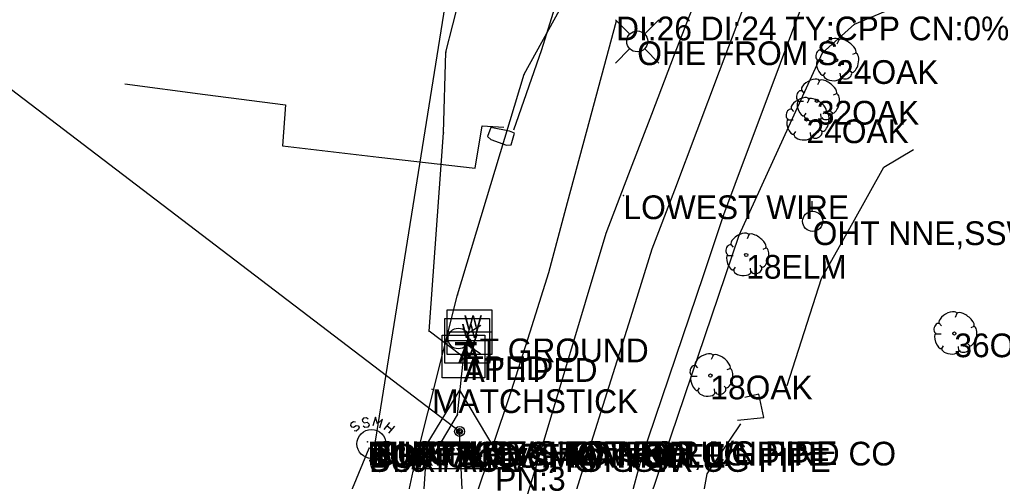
# Model space of a CAD drawing. Extents: x 997398 to 1003416, y 334596 to 337085.
# Drawn here: x 999162 to 999369.2, y 335640.6 to 335737.9 of the extents above; entities that cross this region are included whole.
import ezdxf

# ---------------------------------------------------------------- set-up
doc = ezdxf.new("R2010")
doc.units = 0
for name, color, linetype in [('Default', 7, 'Continuous'), ('S_CURB', 7, 'Continuous'), ('S_DITCHLINE', 7, 'Continuous'), ('S_EDGE_CONCRETE', 7, 'Continuous'), ('S_EDGE_PAVEMENT', 7, 'Continuous'), ('S_ELECTRIC_UTILITIES_ANNOT', 7, 'Continuous'), ('S_FIBER_OPTIC_CABLE', 7, 'Continuous'), ('S_FIBER_OPTIC_CABLE_ANNOT', 7, 'Continuous'), ('S_GRD_PT_SYM', 7, 'Continuous'), ('S_MANHOLE_ANNOT', 7, 'Continuous'), ('S_MISC_TOPO_POINT', 7, 'Continuous'), ('S_PAVEMENT_CROWN', 7, 'Continuous'), ('S_PRIMARY_CTL', 7, 'Continuous'), ('S_PRIMARY_CTL_ANNOT', 7, 'Continuous'), ('S_SANITARY_SEWER', 7, 'Continuous'), ('S_SANITARY_SEWER_ANNOT', 7, 'Continuous'), ('S_SIDE_DRAIN_ANNOT', 7, 'Continuous'), ('S_TELEPHONE_UTILITIES', 7, 'Continuous'), ('S_TELEPHONE_UTILITIES_ANNOT', 7, 'Continuous'), ('S_TREE', 7, 'Continuous'), ('S_TREE_ANNOT', 7, 'Continuous'), ('S_UTILITY_POLE', 7, 'Continuous'), ('S_UTILITY_POLE_ANNOT', 7, 'Continuous'), ('S_UTL_PT_SYM', 7, 'Continuous'), ('S_WATER_UTILITIES', 7, 'Continuous'), ('S_WATER_UTILITIES_ANNOT', 7, 'Continuous')]:
    doc.layers.add(name, color=color, linetype=linetype)

msp = doc.modelspace()

# ---------------------------------------------------------------- linework, layer by layer
at = {"layer": 'Default'}
for p, q in [((999254.77, 335651.12), (998964.3, 335872.43)), ((999272.07, 335256.17), (999254.77, 335651.12))]:
    msp.add_line(p, q, dxfattribs=at)
at = {"layer": 'S_CURB'}
msp.add_lwpolyline([(999266.19, 335714.69), (999272.09, 335731.57), (999275.58, 335742.68), (999279.48, 335749.62), (999286.56, 335754.18), (999294.45, 335756.63), (999296.19, 335756.83)], dxfattribs=at)
at = {"layer": 'S_DITCHLINE'}
for points in [[(999287.81, 335737.53), (999281.43, 335714.1), (999277.48, 335699.31), (999273.53, 335684.53), (999269.56, 335672.01), (999265.58, 335659.49), (999257.69, 335636), (999252.77, 335619.88)], [(999323.8, 335660.76), (999331.07, 335683.36), (999337.63, 335695.08), (999344.19, 335706.81), (999350.44, 335710.54)], [(999279.93, 335526.04), (999283.42, 335541.33), (999286.91, 335556.62), (999292.97, 335577.81), (999299.03, 335599), (999303, 335620.58), (999306.97, 335642.16), (999314.07, 335652.72)]]:
    msp.add_lwpolyline(points, dxfattribs=at)
at = {"layer": 'S_EDGE_CONCRETE'}
for points in [[(999266.37, 335713.96), (999265.31, 335714.36), (999261.35, 335715.12), (999260.65, 335713.27), (999261.34, 335712.62), (999264.66, 335711.39), (999265.63, 335711.53)], [(999265.63, 335711.53), (999266.37, 335713.96)], [(999313.33, 335653.52), (999318.9, 335654.07), (999317.87, 335658.97), (999314.93, 335658.3)]]:
    msp.add_lwpolyline(points, dxfattribs=at)
at = {"layer": 'S_EDGE_PAVEMENT'}
for points in [[(999259.87, 335596.96), (999264.04, 335615.85), (999268.21, 335634.73), (999272.57, 335649.27), (999276.93, 335663.8), (999281.3, 335678.34), (999285.66, 335692.87), (999290.47, 335705.41), (999295.28, 335717.95), (999300.08, 335730.5), (999304.89, 335743.04), (999311.07, 335757.48), (999317.24, 335771.92), (999323.96, 335787.59), (999330.67, 335803.27), (999334.33, 335812.1)], [(999352.59, 335804.28), (999348.8, 335795.55), (999343.98, 335783.6), (999339.17, 335771.64), (999334.35, 335759.69), (999329.54, 335747.73), (999324.76, 335734.99), (999319.98, 335722.25), (999315.21, 335709.51), (999310.43, 335696.77), (999306.09, 335683.91), (999301.75, 335671.05), (999297.41, 335658.19), (999293.07, 335645.33), (999289.63, 335632.59), (999286.2, 335619.85), (999282.76, 335607.12), (999279.33, 335594.38)], [(999184.24, 335724.34), (999201.16, 335722.13), (999218.08, 335719.91), (999217.45, 335711.3), (999237.76, 335708.93), (999258.08, 335706.56), (999259.56, 335715.48), (999264.13, 335715.19)]]:
    msp.add_lwpolyline(points, dxfattribs=at)
at = {"layer": 'S_FIBER_OPTIC_CABLE'}
for p, q in [((999268.37, 335726.35), (999282.47, 335752.03)), ((999251.87, 335731.03), (999255.29, 335744.38)), ((999338.02, 335736.93), (999346.74, 335740.59)), ((999331.26, 335730.91), (999338.02, 335736.93)), ((999251.36, 335714.01), (999251.87, 335731.03)), ((999313.68, 335692.48), (999331.26, 335730.91)), ((999254.36, 335679.9), (999268.37, 335726.35)), ((999248.33, 335672.22), (999251.36, 335714.01)), ((999295.04, 335637.34), (999313.68, 335692.48)), ((999245.02, 335642.72), (999254.36, 335679.9)), ((999255.06, 335667.18), (999248.33, 335672.22)), ((999254.35, 335654.64), (999255.61, 335666.56)), ((999255.61, 335666.56), (999255.06, 335667.18)), ((999247.58, 335643.26), (999254.35, 335654.64)), ((999239.4, 335617.34), (999245.02, 335642.72)), ((999246.94, 335633.43), (999247.58, 335643.26))]:
    msp.add_line(p, q, dxfattribs=at)
at = {"layer": 'S_GRD_PT_SYM'}
for points in [[(999289.32, 335700.84), (999289.32, 335700.89), (999289.32, 335700.84), (999289.27, 335700.84), (999289.32, 335700.84), (999289.32, 335700.79), (999289.32, 335700.84), (999289.37, 335700.84)], [(999235.34, 335648.94), (999235.34, 335648.99), (999235.34, 335648.94), (999235.29, 335648.94), (999235.34, 335648.94), (999235.34, 335648.89), (999235.34, 335648.94), (999235.39, 335648.94)], [(999237.04, 335649.04), (999237.04, 335649.09), (999237.04, 335649.04), (999236.99, 335649.04), (999237.04, 335649.04), (999237.04, 335648.99), (999237.04, 335649.04), (999237.09, 335649.04)], [(999235.68, 335647.6), (999235.68, 335647.65), (999235.68, 335647.6), (999235.63, 335647.6), (999235.68, 335647.6), (999235.68, 335647.55), (999235.68, 335647.6), (999235.73, 335647.6)]]:
    msp.add_lwpolyline(points, dxfattribs=at)
at = {"layer": 'S_PAVEMENT_CROWN'}
msp.add_lwpolyline([(999277.22, 335631.74), (999281.77, 335646.2), (999286.31, 335660.66), (999290.86, 335675.12), (999295.4, 335689.58), (999300.12, 335702.05), (999304.83, 335714.52), (999309.55, 335726.99), (999314.27, 335739.46), (999320.77, 335755.48), (999327.27, 335771.5), (999333.35, 335785.79), (999339.42, 335800.08), (999343.03, 335808.38)], dxfattribs=at)
at = {"layer": 'S_PRIMARY_CTL'}
for p, q in [((999254.77, 335659.82), (999244.74, 335643.31)), ((999254.77, 335659.82), (999264.59, 335643.31)), ((999244.74, 335643.31), (999264.59, 335643.31))]:
    msp.add_line(p, q, dxfattribs=at)
for radius in [1.04, 0.609, 0.344]:
    msp.add_circle((999254.77, 335651.12), radius, dxfattribs=at)
at = {"layer": 'S_SANITARY_SEWER'}
for p, q in [((999237.04, 335649.04), (999255.03, 335761.15)), ((999231.87, 335652.78), (999231.79, 335652.39)), ((999231.79, 335652.39), (999231.99, 335652.12)), ((999232.41, 335653.17), (999231.87, 335652.78)), ((999231.99, 335652.12), (999232.41, 335652.01)), ((999232.84, 335653.09), (999232.41, 335653.17)), ((999232.41, 335652.01), (999232.96, 335652.35)), ((999232.96, 335652.35), (999233.42, 335652.28)), ((999233.42, 335652.28), (999233.58, 335652.01)), ((999233.58, 335652.01), (999233.5, 335651.58)), ((999238.85, 335651.54), (999240.09, 335653.01)), ((999239.5, 335652.32), (999240.47, 335651.5)), ((999241.05, 335652.2), (999239.81, 335650.73)), ((999232.96, 335651.19), (999232.57, 335651.27)), ((999233.5, 335651.58), (999232.96, 335651.19)), ((999196.73, 335553), (999235.68, 335647.6))]:
    msp.add_line(p, q, dxfattribs=at)
for points in [[(999237.95, 335651.85), (999238.5, 335653.71), (999237.45, 335652.7), (999237.06, 335654.14), (999236.52, 335652.28)], [(999235.51, 335653.71), (999235.16, 335653.98), (999234.51, 335653.9), (999234.27, 335653.56), (999234.31, 335653.25), (999234.66, 335652.94), (999235.28, 335653.05), (999235.67, 335652.74), (999235.71, 335652.43), (999235.44, 335652.04), (999234.82, 335651.97), (999234.47, 335652.24)]]:
    msp.add_lwpolyline(points, dxfattribs=at)
msp.add_circle((999236.2, 335648.48), 3.05, dxfattribs=at)
at = {"layer": 'S_TELEPHONE_UTILITIES'}
msp.add_lwpolyline([(999251.07, 335662.43), (999251.07, 335671.43), (999260.07, 335671.43), (999260.07, 335662.43)], close=True, dxfattribs=at)
at = {"layer": 'S_TREE'}
for p, q in [((999334.71, 335733.58), (999334.32, 335732.72)), ((999330.91, 335731.56), (999331.41, 335730.98)), ((999338.27, 335730.79), (999337.61, 335730.51)), ((999330.25, 335729.24), (999331.38, 335729.24)), ((999331.41, 335726.06), (999331.88, 335726.76)), ((999335.1, 335725.79), (999335.02, 335726.56)), ((999337.5, 335726.68), (999337.03, 335727.1)), ((999330.63, 335725.01), (999330.25, 335724.16)), ((999326.84, 335722.99), (999327.34, 335722.41)), ((999326.18, 335720.67), (999327.3, 335720.67)), ((999328.45, 335721.1), (999328.07, 335720.25)), ((999334.2, 335722.22), (999333.54, 335721.95)), ((999324.66, 335719.08), (999325.16, 335718.5)), ((999332.02, 335718.31), (999331.36, 335718.04)), ((999333.42, 335718.11), (999332.96, 335718.54)), ((999324, 335716.76), (999325.12, 335716.76)), ((999327.34, 335717.49), (999327.8, 335718.19)), ((999331.02, 335717.22), (999330.94, 335718)), ((999325.16, 335713.58), (999325.62, 335714.28)), ((999328.84, 335713.31), (999328.76, 335714.08)), ((999331.24, 335714.2), (999330.78, 335714.63)), ((999315.75, 335692.54), (999315.36, 335691.69)), ((999311.95, 335690.52), (999312.46, 335689.94)), ((999319.31, 335689.75), (999318.66, 335689.48)), ((999311.29, 335688.2), (999312.42, 335688.2)), ((999312.46, 335685.02), (999312.92, 335685.72)), ((999316.14, 335684.75), (999316.06, 335685.52)), ((999318.54, 335685.64), (999318.07, 335686.07)), ((999359.62, 335675.99), (999359.23, 335675.14)), ((999355.82, 335673.98), (999356.32, 335673.39)), ((999363.18, 335673.2), (999362.52, 335672.93)), ((999355.16, 335671.65), (999356.28, 335671.65)), ((999356.32, 335668.47), (999356.79, 335669.17)), ((999360, 335668.2), (999359.93, 335668.98)), ((999362.41, 335669.09), (999361.94, 335669.52)), ((999308.2, 335667.13), (999307.81, 335666.28)), ((999304.4, 335665.11), (999304.9, 335664.53)), ((999303.74, 335662.79), (999304.86, 335662.79)), ((999311.76, 335664.34), (999311.1, 335664.07)), ((999304.9, 335659.61), (999305.37, 335660.31)), ((999310.99, 335660.23), (999310.52, 335660.66)), ((999308.58, 335659.34), (999308.51, 335660.11))]:
    msp.add_line(p, q, dxfattribs=at)
for centre in [(999334.15, 335729.33), (999330.08, 335720.76), (999327.9, 335716.85), (999315.19, 335688.29), (999359.06, 335671.75), (999307.64, 335662.88)]:
    msp.add_circle(centre, 0.341, dxfattribs=at)
for centre, major_axis, ratio, start_param, end_param in [((999332.81, 335732.53), (1.86, 1.08), 0.471018, 0, 3.141593), ((999336.47, 335732.21), (-1.81, 1.36), 0.405113, 3.141593, 6.283186), ((999330.58, 335730.42), (0.31, 1.03), 0.646762, 0, 3.141593), ((999337.82, 335728.8), (0.46, 2.04), 0.482994, 3.141593, 6.283185), ((999330.88, 335727.77), (-0.61, 1.6), 0.420543, 6.283185, 9.424777), ((999336.3, 335726.28), (1.09, 0.46), 0.711534, 3.141592, 6.283185), ((999328.74, 335723.97), (1.86, 1.08), 0.471018, 0, 3.141593), ((999332.39, 335723.64), (-1.81, 1.36), 0.405113, 3.141593, 6.283186), ((999333.34, 335725.99), (-1.83, 0.19), 0.529943, 0, 3.141593), ((999326.5, 335721.85), (0.31, 1.03), 0.646762, 0, 3.141593), ((999326.56, 335720.06), (1.86, 1.08), 0.471018, 0, 3.141593), ((999326.81, 335719.2), (-0.61, 1.6), 0.420543, 6.283185, 9.424777), ((999330.21, 335719.73), (-1.81, 1.36), 0.405113, 3.141593, 6.283186), ((999333.75, 335720.23), (0.46, 2.04), 0.482994, 3.141593, 6.283185), ((999324.32, 335717.94), (0.31, 1.03), 0.646762, 0, 3.141593), ((999331.57, 335716.32), (0.46, 2.04), 0.482994, 3.141593, 6.283185), ((999324.63, 335715.29), (-0.61, 1.6), 0.420543, 6.283185, 9.424777), ((999329.27, 335717.42), (-1.83, 0.19), 0.529943, 0, 3.141593), ((999332.23, 335717.71), (1.09, 0.46), 0.711534, 3.141592, 6.283185), ((999330.05, 335713.8), (1.09, 0.46), 0.711534, 3.141592, 6.283185), ((999327.09, 335713.51), (-1.83, 0.19), 0.529943, 0, 3.141593), ((999313.86, 335691.49), (1.86, 1.08), 0.471018, 0, 3.141593), ((999317.51, 335691.17), (-1.81, 1.36), 0.405113, 3.141593, 6.283186), ((999311.62, 335689.38), (0.31, 1.03), 0.646762, 0, 3.141593), ((999318.87, 335687.76), (0.46, 2.04), 0.482994, 3.141593, 6.283185), ((999311.93, 335686.73), (-0.61, 1.6), 0.420543, 6.283185, 9.424777), ((999314.39, 335684.95), (-1.83, 0.19), 0.529943, 0, 3.141593), ((999317.34, 335685.24), (1.09, 0.46), 0.711534, 3.141592, 6.283185), ((999357.72, 335674.95), (1.86, 1.08), 0.471018, 0, 3.141593), ((999361.38, 335674.62), (-1.81, 1.36), 0.405113, 3.141593, 6.283186), ((999355.49, 335672.83), (0.31, 1.03), 0.646762, 0, 3.141593), ((999362.73, 335671.22), (0.46, 2.04), 0.482994, 3.141593, 6.283185), ((999355.79, 335670.18), (-0.61, 1.6), 0.420543, 6.283185, 9.424777), ((999358.25, 335668.4), (-1.83, 0.19), 0.529943, 0, 3.141593), ((999361.21, 335668.69), (1.09, 0.46), 0.711534, 3.141592, 6.283185), ((999306.3, 335666.09), (1.86, 1.08), 0.471018, 0, 3.141593), ((999309.96, 335665.76), (-1.81, 1.36), 0.405113, 3.141593, 6.283186), ((999304.07, 335663.97), (0.31, 1.03), 0.646762, 0, 3.141593), ((999311.31, 335662.35), (0.46, 2.04), 0.482994, 3.141593, 6.283185), ((999304.37, 335661.32), (-0.61, 1.6), 0.420543, 6.283185, 9.424777), ((999309.79, 335659.83), (1.09, 0.46), 0.711534, 3.141592, 6.283185), ((999306.83, 335659.54), (-1.83, 0.19), 0.529943, 0, 3.141593)]:
    msp.add_ellipse(centre, major_axis=major_axis, ratio=ratio, start_param=start_param, end_param=end_param, dxfattribs=at)
at = {"layer": 'S_UTILITY_POLE'}
for p, q in [((999290.62, 335734.87), (999287.64, 335737.86)), ((999293.8, 335734.87), (999296.78, 335737.86)), ((999290.62, 335731.69), (999287.64, 335728.71)), ((999293.8, 335731.69), (999296.78, 335728.71)), ((999329.07, 335697.52), (999329.07, 335699.63))]:
    msp.add_line(p, q, dxfattribs=at)
for centre, radius in [((999292.22, 335733.29), 2.21), ((999329.2, 335695.38), 2.13)]:
    msp.add_circle(centre, radius, dxfattribs=at)
at = {"layer": 'S_UTL_PT_SYM'}
for points in [[(999338.02, 335736.93), (999338.02, 335736.98), (999338.02, 335736.93), (999337.97, 335736.93), (999338.02, 335736.93), (999338.02, 335736.88), (999338.02, 335736.93), (999338.07, 335736.93)], [(999251.87, 335731.03), (999251.87, 335731.08), (999251.87, 335731.03), (999251.82, 335731.03), (999251.87, 335731.03), (999251.87, 335730.98), (999251.87, 335731.03), (999251.92, 335731.03)], [(999331.26, 335730.91), (999331.26, 335730.96), (999331.26, 335730.91), (999331.21, 335730.91), (999331.26, 335730.91), (999331.26, 335730.86), (999331.26, 335730.91), (999331.31, 335730.91)], [(999268.37, 335726.35), (999268.37, 335726.4), (999268.37, 335726.35), (999268.32, 335726.35), (999268.37, 335726.35), (999268.37, 335726.3), (999268.37, 335726.35), (999268.42, 335726.35)], [(999251.36, 335714.01), (999251.36, 335714.06), (999251.36, 335714.01), (999251.31, 335714.01), (999251.36, 335714.01), (999251.36, 335713.96), (999251.36, 335714.01), (999251.41, 335714.01)], [(999289.32, 335700.84), (999289.32, 335700.89), (999289.32, 335700.84), (999289.27, 335700.84), (999289.32, 335700.84), (999289.32, 335700.79), (999289.32, 335700.84), (999289.37, 335700.84)], [(999313.68, 335692.48), (999313.68, 335692.53), (999313.68, 335692.48), (999313.63, 335692.48), (999313.68, 335692.48), (999313.68, 335692.43), (999313.68, 335692.48), (999313.73, 335692.48)], [(999254.36, 335679.9), (999254.36, 335679.95), (999254.36, 335679.9), (999254.31, 335679.9), (999254.36, 335679.9), (999254.36, 335679.85), (999254.36, 335679.9), (999254.41, 335679.9)], [(999248.33, 335672.22), (999248.33, 335672.27), (999248.33, 335672.22), (999248.28, 335672.22), (999248.33, 335672.22), (999248.33, 335672.17), (999248.33, 335672.22), (999248.38, 335672.22)], [(999255.06, 335667.18), (999255.06, 335667.23), (999255.06, 335667.18), (999255.01, 335667.18), (999255.06, 335667.18), (999255.06, 335667.13), (999255.06, 335667.18), (999255.11, 335667.18)], [(999255.61, 335666.56), (999255.61, 335666.61), (999255.61, 335666.56), (999255.56, 335666.56), (999255.61, 335666.56), (999255.61, 335666.51), (999255.61, 335666.56), (999255.66, 335666.56)], [(999248.97, 335659.99), (999248.97, 335660.04), (999248.97, 335659.99), (999248.92, 335659.99), (999248.97, 335659.99), (999248.97, 335659.94), (999248.97, 335659.99), (999249.02, 335659.99)], [(999254.35, 335654.64), (999254.35, 335654.69), (999254.35, 335654.64), (999254.3, 335654.64), (999254.35, 335654.64), (999254.35, 335654.59), (999254.35, 335654.64), (999254.4, 335654.64)], [(999235.34, 335648.94), (999235.34, 335648.99), (999235.34, 335648.94), (999235.29, 335648.94), (999235.34, 335648.94), (999235.34, 335648.89), (999235.34, 335648.94), (999235.39, 335648.94)], [(999236.2, 335648.48), (999236.2, 335648.53), (999236.2, 335648.48), (999236.15, 335648.48), (999236.2, 335648.48), (999236.2, 335648.43), (999236.2, 335648.48), (999236.25, 335648.48)], [(999237.04, 335649.04), (999237.04, 335649.09), (999237.04, 335649.04), (999236.99, 335649.04), (999237.04, 335649.04), (999237.04, 335648.99), (999237.04, 335649.04), (999237.09, 335649.04)], [(999235.68, 335647.6), (999235.68, 335647.65), (999235.68, 335647.6), (999235.63, 335647.6), (999235.68, 335647.6), (999235.68, 335647.55), (999235.68, 335647.6), (999235.73, 335647.6)], [(999245.02, 335642.72), (999245.02, 335642.77), (999245.02, 335642.72), (999244.97, 335642.72), (999245.02, 335642.72), (999245.02, 335642.67), (999245.02, 335642.72), (999245.07, 335642.72)], [(999247.58, 335643.26), (999247.58, 335643.31), (999247.58, 335643.26), (999247.53, 335643.26), (999247.58, 335643.26), (999247.58, 335643.21), (999247.58, 335643.26), (999247.63, 335643.26)]]:
    msp.add_lwpolyline(points, dxfattribs=at)
at = {"layer": 'S_WATER_UTILITIES'}
for p, q in [((999251.68, 335674.94), (999261.1, 335674.94)), ((999251.68, 335665.52), (999251.68, 335674.94)), ((999252.18, 335676.76), (999261.6, 335676.76)), ((999252.18, 335667.34), (999252.18, 335676.76)), ((999261.1, 335674.94), (999261.1, 335665.52)), ((999261.6, 335676.76), (999261.6, 335667.34)), ((999256.43, 335671.75), (999259.25, 335673.48)), ((999252.18, 335672.07), (999261.6, 335672.07)), ((999251.68, 335670.25), (999261.1, 335670.25)), ((999256.3, 335669.44), (999259.21, 335667.51)), ((999261.6, 335667.34), (999252.18, 335667.34)), ((999261.1, 335665.52), (999251.68, 335665.52))]:
    msp.add_line(p, q, dxfattribs=at)
msp.add_circle((999254.52, 335670.69), 2.18, dxfattribs=at)

# ---------------------------------------------------------------- texts
at = {"layer": 'S_ELECTRIC_UTILITIES_ANNOT'}
msp.add_text('LOWEST WIRE', height=5, dxfattribs=at).set_placement((999289.32, 335695.84))
at = {"layer": 'S_FIBER_OPTIC_CABLE_ANNOT'}
for s, p in [('AT TPED', (999255.61, 335661.56)), ('MATCHSTICK', (999248.97, 335654.99))]:
    msp.add_text(s, height=5, dxfattribs=at).set_placement(p)
at = {"layer": 'S_MANHOLE_ANNOT'}
msp.add_text('BOTTOM OF MANHOLE', height=5, dxfattribs=at).set_placement((999236.2, 335643.48))
at = {"layer": 'S_MISC_TOPO_POINT'}
for p in [(999235.34, 335643.94), (999237.04, 335644.04), (999235.68, 335642.6)]:
    msp.add_text('SURFACE SHOT FOR UG PIPE', height=5, dxfattribs=at).set_placement(p)
at = {"layer": 'S_PRIMARY_CTL'}
msp.add_text('CTL', height=5, rotation=360, dxfattribs=at).set_placement((999248.18, 335644.05))
at = {"layer": 'S_PRIMARY_CTL_ANNOT'}
msp.add_text('PN:3', height=5, dxfattribs=at).set_placement((999262.27, 335638.62))
at = {"layer": 'S_SANITARY_SEWER_ANNOT'}
for s, p in [('DI:4 TY:PVC TO WNW,C/N FIND CO', (999235.34, 335643.94)), ('TOP CL OF MANHOLE', (999236.2, 335643.48)), ('DI:8 TY:PVC TO NE', (999237.04, 335644.04)), ('DI:6 TY:PVC TO SSW', (999235.68, 335642.6))]:
    msp.add_text(s, height=5, dxfattribs=at).set_placement(p)
at = {"layer": 'S_SIDE_DRAIN_ANNOT'}
msp.add_text('DI:26 DI:24 TY:CPP CN:0% FILL', height=5, dxfattribs=at).set_placement((999287.77, 335733.51))
at = {"layer": 'S_TELEPHONE_UTILITIES'}
msp.add_text('T', height=6, rotation=360, dxfattribs=at).set_placement((999253.64, 335663.93))
at = {"layer": 'S_TELEPHONE_UTILITIES_ANNOT'}
msp.add_text('TPED', height=5, dxfattribs=at).set_placement((999255.8, 335661.94))
at = {"layer": 'S_TREE_ANNOT'}
for s, p in [('24OAK', (999334.15, 335724.33)), ('32OAK', (999330.08, 335715.76)), ('24OAK', (999327.9, 335711.85)), ('18ELM', (999315.19, 335683.29)), ('36OAK', (999359.06, 335666.75)), ('18OAK', (999307.64, 335657.88))]:
    msp.add_text(s, height=5, dxfattribs=at).set_placement(p)
at = {"layer": 'S_UTILITY_POLE_ANNOT'}
for s, p in [('OHE FROM S.', (999292.22, 335728.29)), ('OHT NNE,SSW', (999329.2, 335690.38))]:
    msp.add_text(s, height=5, dxfattribs=at).set_placement(p)
at = {"layer": 'S_WATER_UTILITIES'}
for s, p in [('W', (999255.73, 335672.6)), ('W', (999255.23, 335670.78)), ('V', (999255.97, 335668.54)), ('V', (999255.47, 335666.72))]:
    msp.add_text(s, height=3, rotation=360, dxfattribs=at).set_placement(p)
at = {"layer": 'S_WATER_UTILITIES_ANNOT'}
msp.add_text('AT GROUND', height=5, dxfattribs=at).set_placement((999254.52, 335665.69))

doc.saveas('drawing.dxf')
